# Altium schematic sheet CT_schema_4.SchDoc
size 144 x 123 mm
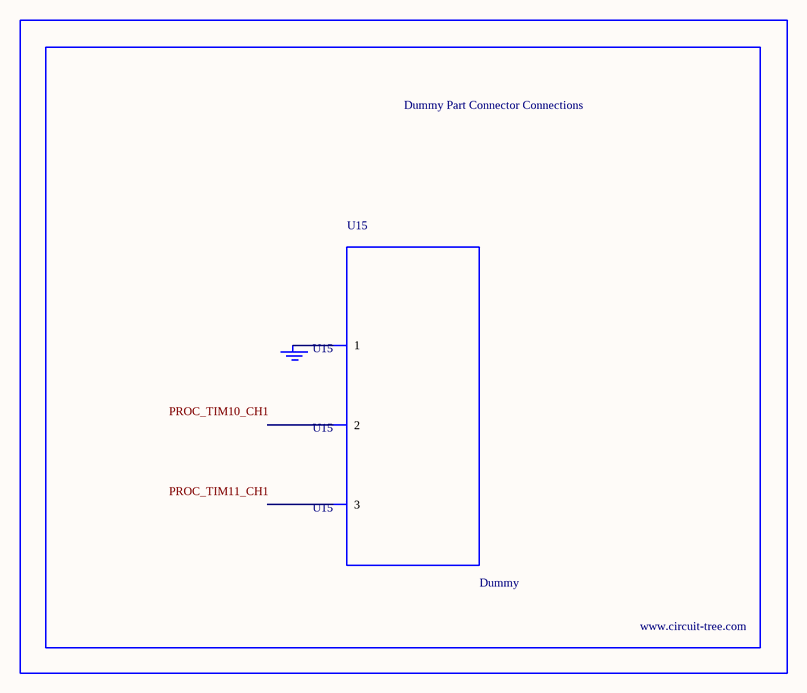
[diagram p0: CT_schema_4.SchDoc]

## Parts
BORDER3  (no value)
GND_INSTANCE_3_0  (no value)
U15  Dummy  [DUMMY_PACKAGE_119]

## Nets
NetGND_INSTANCE_3_0_0: GND_INSTANCE_3_0.0(GND) U15.1

Not connected (* = marked no-connect by the designer): U15 2 3

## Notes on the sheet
- Labels drawn without touching a wire or pin: PROC_TIM10_CH1, PROC_TIM11_CH1

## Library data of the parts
BORDER3 = BORDER_PAGE3
GND_INSTANCE_3_0 = GND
